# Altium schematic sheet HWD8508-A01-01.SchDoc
size A3; SheetNumber: 0; SheetTotal: 0; PageSetup: Record=PageOptions¦CenterHorizontal=True¦CenterVertical=True¦PrintScale=0.68¦XCorrection=1.00¦YCorrection=1.00¦PrintKind=0¦BorderSize=5000000¦LeftOffset=0¦BottomOffset=0¦Orientation=2¦PaperLength=1000¦PaperWidth=1000¦Scale=100¦PaperSource=15¦PrintQuality=-3¦MediaType=1¦DitherType=10¦PrintScaleMode=1¦PaperKind=Letter¦PaperIndex=1
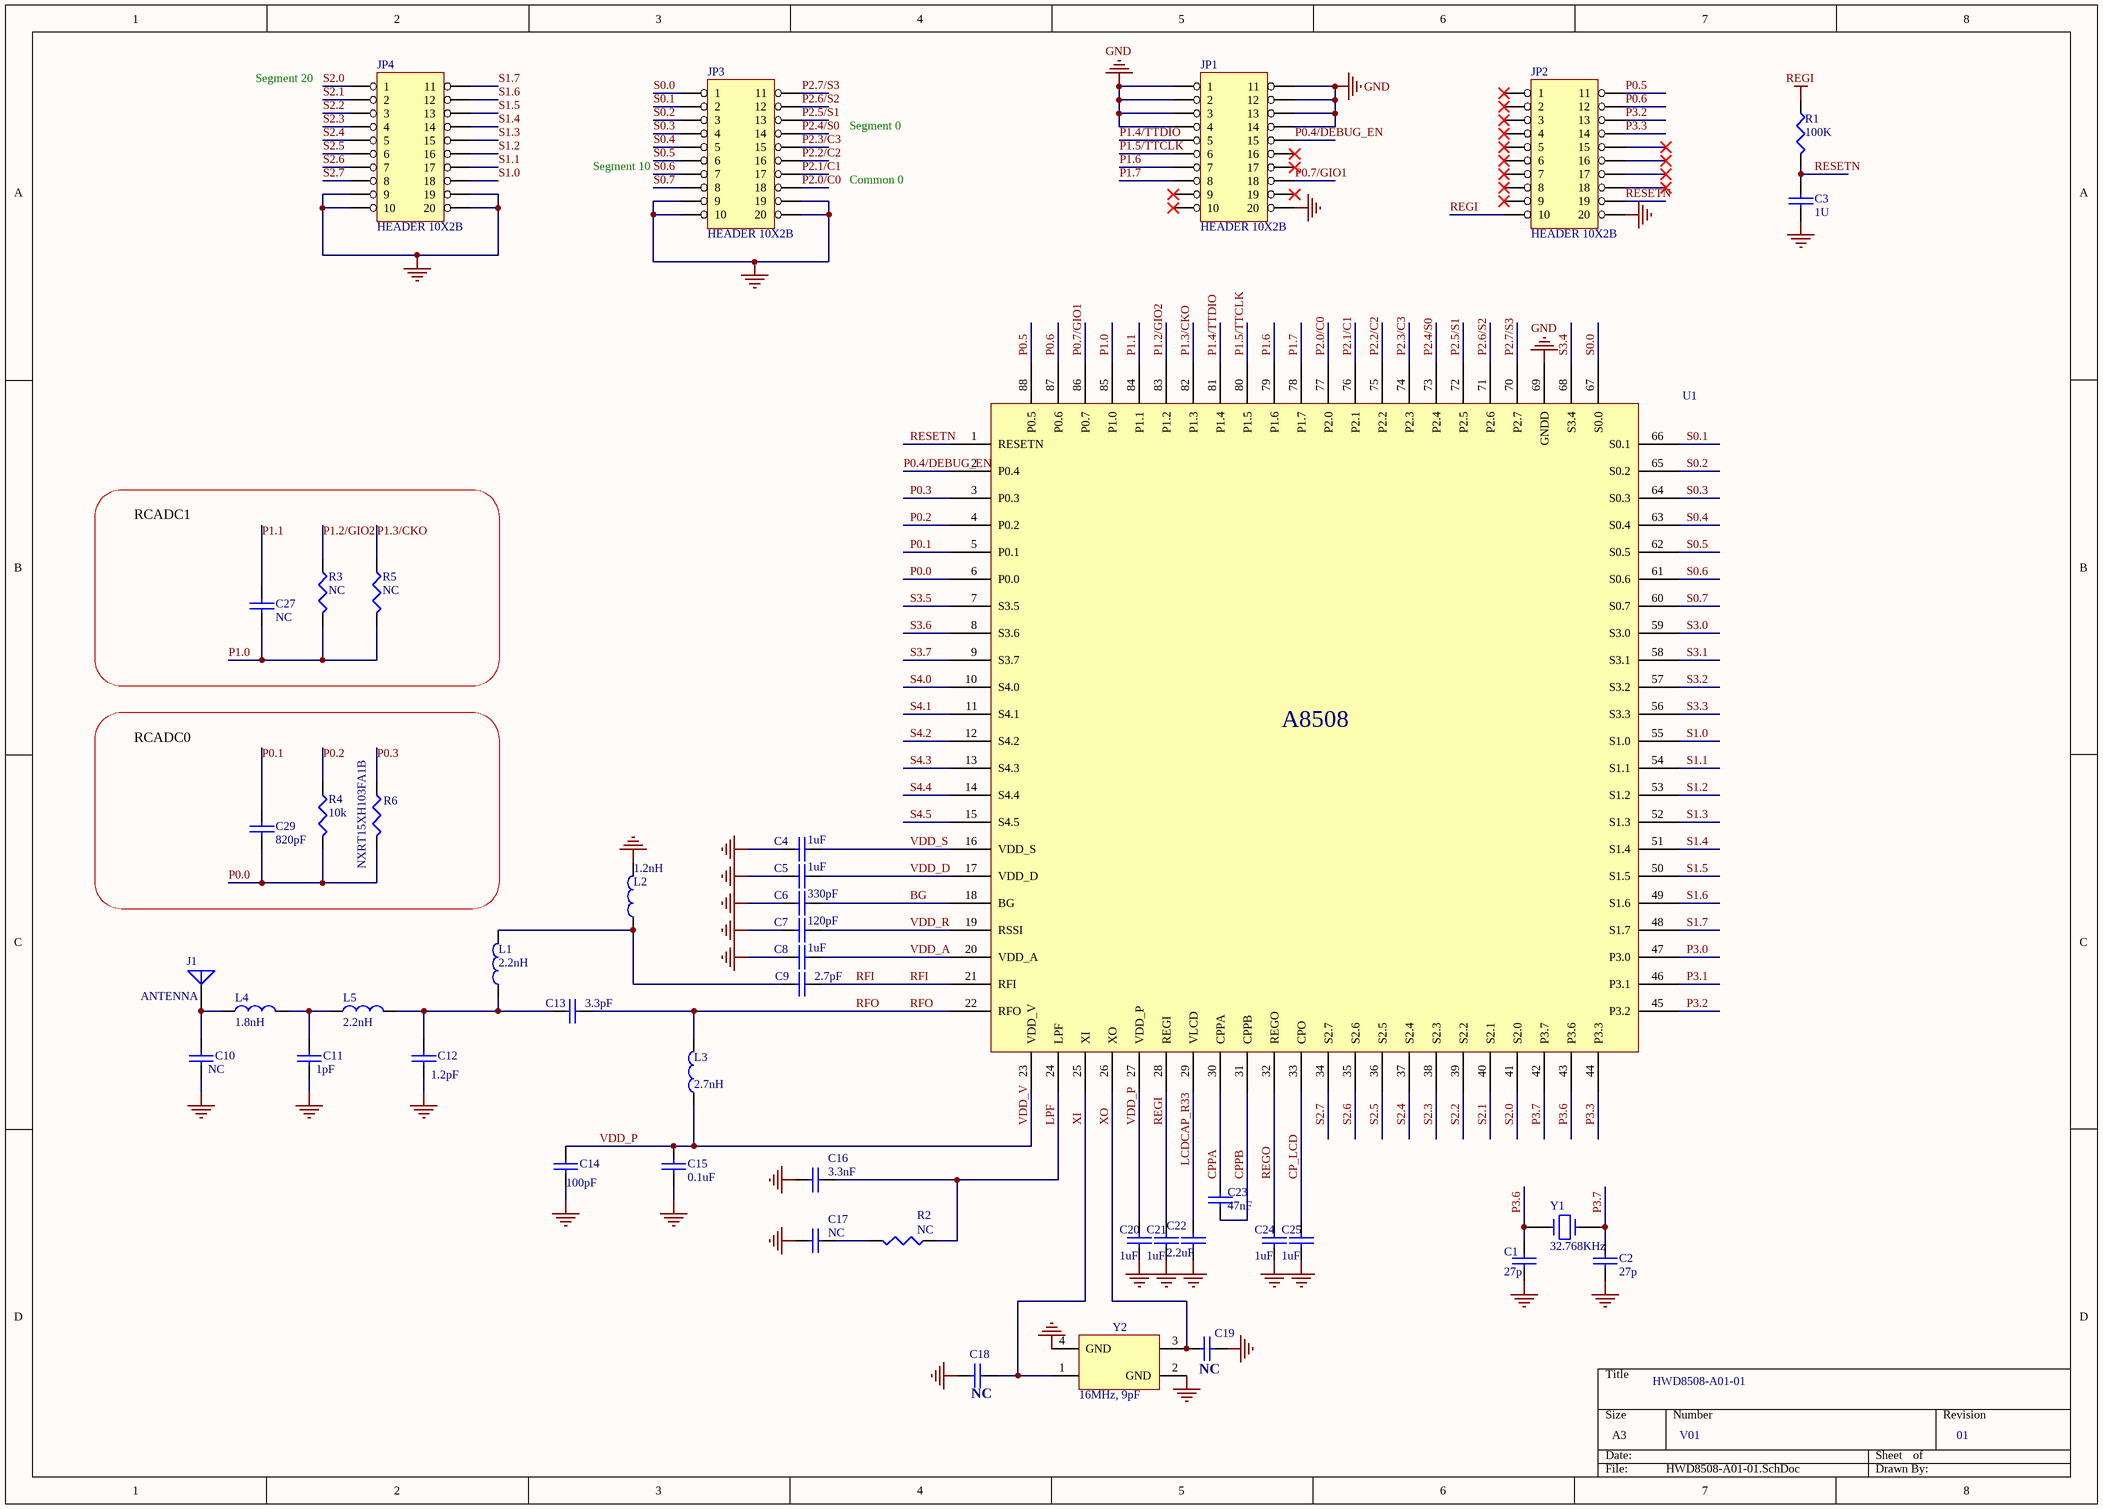
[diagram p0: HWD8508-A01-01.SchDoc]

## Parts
C1  27p  [0402]
C2  27p  [0402]
C3  1U  [0402]
C4  1uF  [0402]
C5  1uF  [0402]
C6  330pF  [0402]
C7  120pF  [0402]
C8  1uF  [0402]
C9  2.7pF  [0402]
C10  NC  [0402]
C11  1pF  [0402]
C12  1.2pF  [0402]
C13  3.3pF  [0402]
C14  100pF  [0402]
C15  0.1uF  [0402]
C16  3.3nF  [0402]
C17  NC  [0402]
C18  NC  [0402]
C19  NC  [0402]
C20  1uF  [0402]
C21  1uF  [0402]
C22  2.2uF  [0402]
C23  47nF  [0402]
C24  1uF  [0402]
C25  1uF  [0402]
C27  NC  [0402]
C29  820pF  [0402]
J1  ANTENNA  [ANT]
JP1  HEADER 10X2B  [YAB-V45P-2X]
JP2  HEADER 10X2B  [YAB-V45P-2X]
JP3  HEADER 10X2B  [PAB-V16P-2X]
JP4  HEADER 10X2B  [PAB-V16P-2X]
L1  2.2nH  [0402]
L2  1.2nH  [0402]
L3  2.7nH  [0402]
L4  1.8nH  [0402]
L5  2.2nH  [0402]
R1  100K  [0402]
R2  NC  [0402]
R3  NC  [0402]
R4  10k  [0402]
R5  NC  [TR]
R6  NXRT15XH103FA1B  [TR]
U1  A8508  [QFN 10*10 88L]
Y1  32.768KHz  [XTAL\32.768K\SMD]
Y2  16MHz, 9pF  [XTAL_3.2*2.5]

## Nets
GND: C1.2 C2.2 C3.2 C4.2 C5.2 C6.2 C7.2 C8.2 C10.1 C11.1 C12.2 C14.2 C15.2 C16.2 C17.2 C18.2 C19.2 C20.2 C21.2 C22.2 C24.2 C25.2 JP1.1 JP1.2 JP1.3 JP1.4 JP1.11 JP1.12 JP1.13 JP1.14 JP1.20 JP2.20 JP3.9 JP3.10 JP3.19 JP3.20 JP4.9 JP4.10 JP4.19 JP4.20 L2.2 U1.69(GNDD) Y2.2(GND) Y2.4(GND)
REGI: C21.1 JP2.10 R1.1 U1.28(REGI)
BG: C6.1 U1.18(BG)
CP_LCD: C25.1 U1.33(CPO)
CPPA: C23.1 U1.30(CPPA)
CPPB: C23.2 U1.31(CPPB)
LCDCAP_R33: C22.1 U1.29(VLCD)
LPF: C16.1 R2.1 U1.24(LPF)
P0.0: C29.1 R4.2 R6.2 U1.6(P0.0)
P0.1: C29.2 U1.5(P0.1)
P0.2: R4.1 U1.4(P0.2)
P0.3: R6.1 U1.3(P0.3)
P0.4/DEBUG_EN: JP1.15 U1.2(P0.4)
P0.5: JP2.11 U1.88(P0.5)
P0.6: JP2.12 U1.87(P0.6)
P0.7/GIO1: JP1.18 U1.86(P0.7)
P1.0: C27.1 R3.2 R5.2 U1.85(P1.0)
P1.1: C27.2 U1.84(P1.1)
P1.2/GIO2: R3.1 U1.83(P1.2)
P1.3/CKO: R5.1 U1.82(P1.3)
P1.4/TTDIO: JP1.5 U1.81(P1.4)
P1.5/TTCLK: JP1.6 U1.80(P1.5)
P1.6: JP1.7 U1.79(P1.6)
P1.7: JP1.8 U1.78(P1.7)
P2.0/C0: JP3.18 U1.77(P2.0)
P2.1/C1: JP3.17 U1.76(P2.1)
P2.2/C2: JP3.16 U1.75(P2.2)
P2.3/C3: JP3.15 U1.74(P2.3)
P2.4/S0: JP3.14 U1.73(P2.4)
P2.5/S1: JP3.13 U1.72(P2.5)
P2.6/S2: JP3.12 U1.71(P2.6)
P2.7/S3: JP3.11 U1.70(P2.7)
P3.0: U1.47(P3.0)
P3.1: U1.46(P3.1)
P3.2: JP2.13 U1.45(P3.2)
P3.3: JP2.14 U1.44(P3.3)
P3.6: C1.1 U1.43(P3.6) Y1.2
P3.7: C2.1 U1.42(P3.7) Y1.1
REGO: C24.1 U1.32(REGO)
RESETN: C3.1 JP2.19 R1.2 U1.1(RESETN)
RFI: C9.1 U1.21(RFI)
RFO: C13.1 L3.2 U1.22(RFO)
S0.0: JP3.1 U1.67(S0.0)
S0.1: JP3.2 U1.66(S0.1)
S0.2: JP3.3 U1.65(S0.2)
S0.3: JP3.4 U1.64(S0.3)
S0.4: JP3.5 U1.63(S0.4)
S0.5: JP3.6 U1.62(S0.5)
S0.6: JP3.7 U1.61(S0.6)
S0.7: JP3.8 U1.60(S0.7)
S1.0: JP4.18 U1.55(S1.0)
S1.1: JP4.17 U1.54(S1.1)
S1.2: JP4.16 U1.53(S1.2)
S1.3: JP4.15 U1.52(S1.3)
S1.4: JP4.14 U1.51(S1.4)
S1.5: JP4.13 U1.50(S1.5)
S1.6: JP4.12 U1.49(S1.6)
S1.7: JP4.11 U1.48(S1.7)
S2.0: JP4.1 U1.41(S2.0)
S2.1: JP4.2 U1.40(S2.1)
S2.2: JP4.3 U1.39(S2.2)
S2.3: JP4.4 U1.38(S2.3)
S2.4: JP4.5 U1.37(S2.4)
S2.5: JP4.6 U1.36(S2.5)
S2.6: JP4.7 U1.35(S2.6)
S2.7: JP4.8 U1.34(S2.7)
S3.0: U1.59(S3.0)
S3.1: U1.58(S3.1)
S3.2: U1.57(S3.2)
S3.3: U1.56(S3.3)
S3.4: U1.68(S3.4)
S3.5: U1.7(S3.5)
S3.6: U1.8(S3.6)
S3.7: U1.9(S3.7)
S4.0: U1.10(S4.0)
S4.1: U1.11(S4.1)
S4.2: U1.12(S4.2)
S4.3: U1.13(S4.3)
S4.4: U1.14(S4.4)
S4.5: U1.15(S4.5)
VDD_A: C8.1 U1.20(VDD_A)
VDD_D: C5.1 U1.17(VDD_D)
VDD_P: C14.1 C15.1 C20.1 L3.1 U1.23(VDD_V) U1.27(VDD_P)  [also labelled VDD_V]
VDD_R: C7.1 U1.19(RSSI)
VDD_S: C4.1 U1.16(VDD_S)
XI: C18.1 U1.25(XI) Y2.1
XO: C19.1 U1.26(XO) Y2.3
NetC9_2: C9.2 L1.2 L2.1
NetC10_2: C10.2 J1.1(A) L4.1
NetC11_2: C11.2 L4.2 L5.1
NetC12_1: C12.1 C13.2 L1.1 L5.2
NetC17_1: C17.1 R2.2

Not connected (* = marked no-connect by the designer): JP1 9* 10* 16* 17* 19*; JP2 1* 2* 3* 4* 5* 6* 7* 8* 9* 15* 16* 17* 18*

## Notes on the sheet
- Segment 20
- Segment 10
- Common 0
- Segment 0
- RCADC1
- RCADC0
- HWD8508-A01-01
- V01
- 01

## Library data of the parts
C1 C2 C23 = C/0603: Chip C
C3 = C/0402: Chip C
C4-C22 C24 C25 C27 C29 = CAP
JP1-JP4 = HEADER 10X2B: Pitch 2.54mm
L1-L5 = L/0402: Chip L
R1 = R/0603: Chip  R
R2-R6 = RES1
U1 = ams100_3a wo DCDC
Y1 = CRYSTAL
Y2 = CRYSTAL/5*3.2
